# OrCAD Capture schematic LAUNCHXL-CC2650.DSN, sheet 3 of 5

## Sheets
3 4_XDS110: size A3
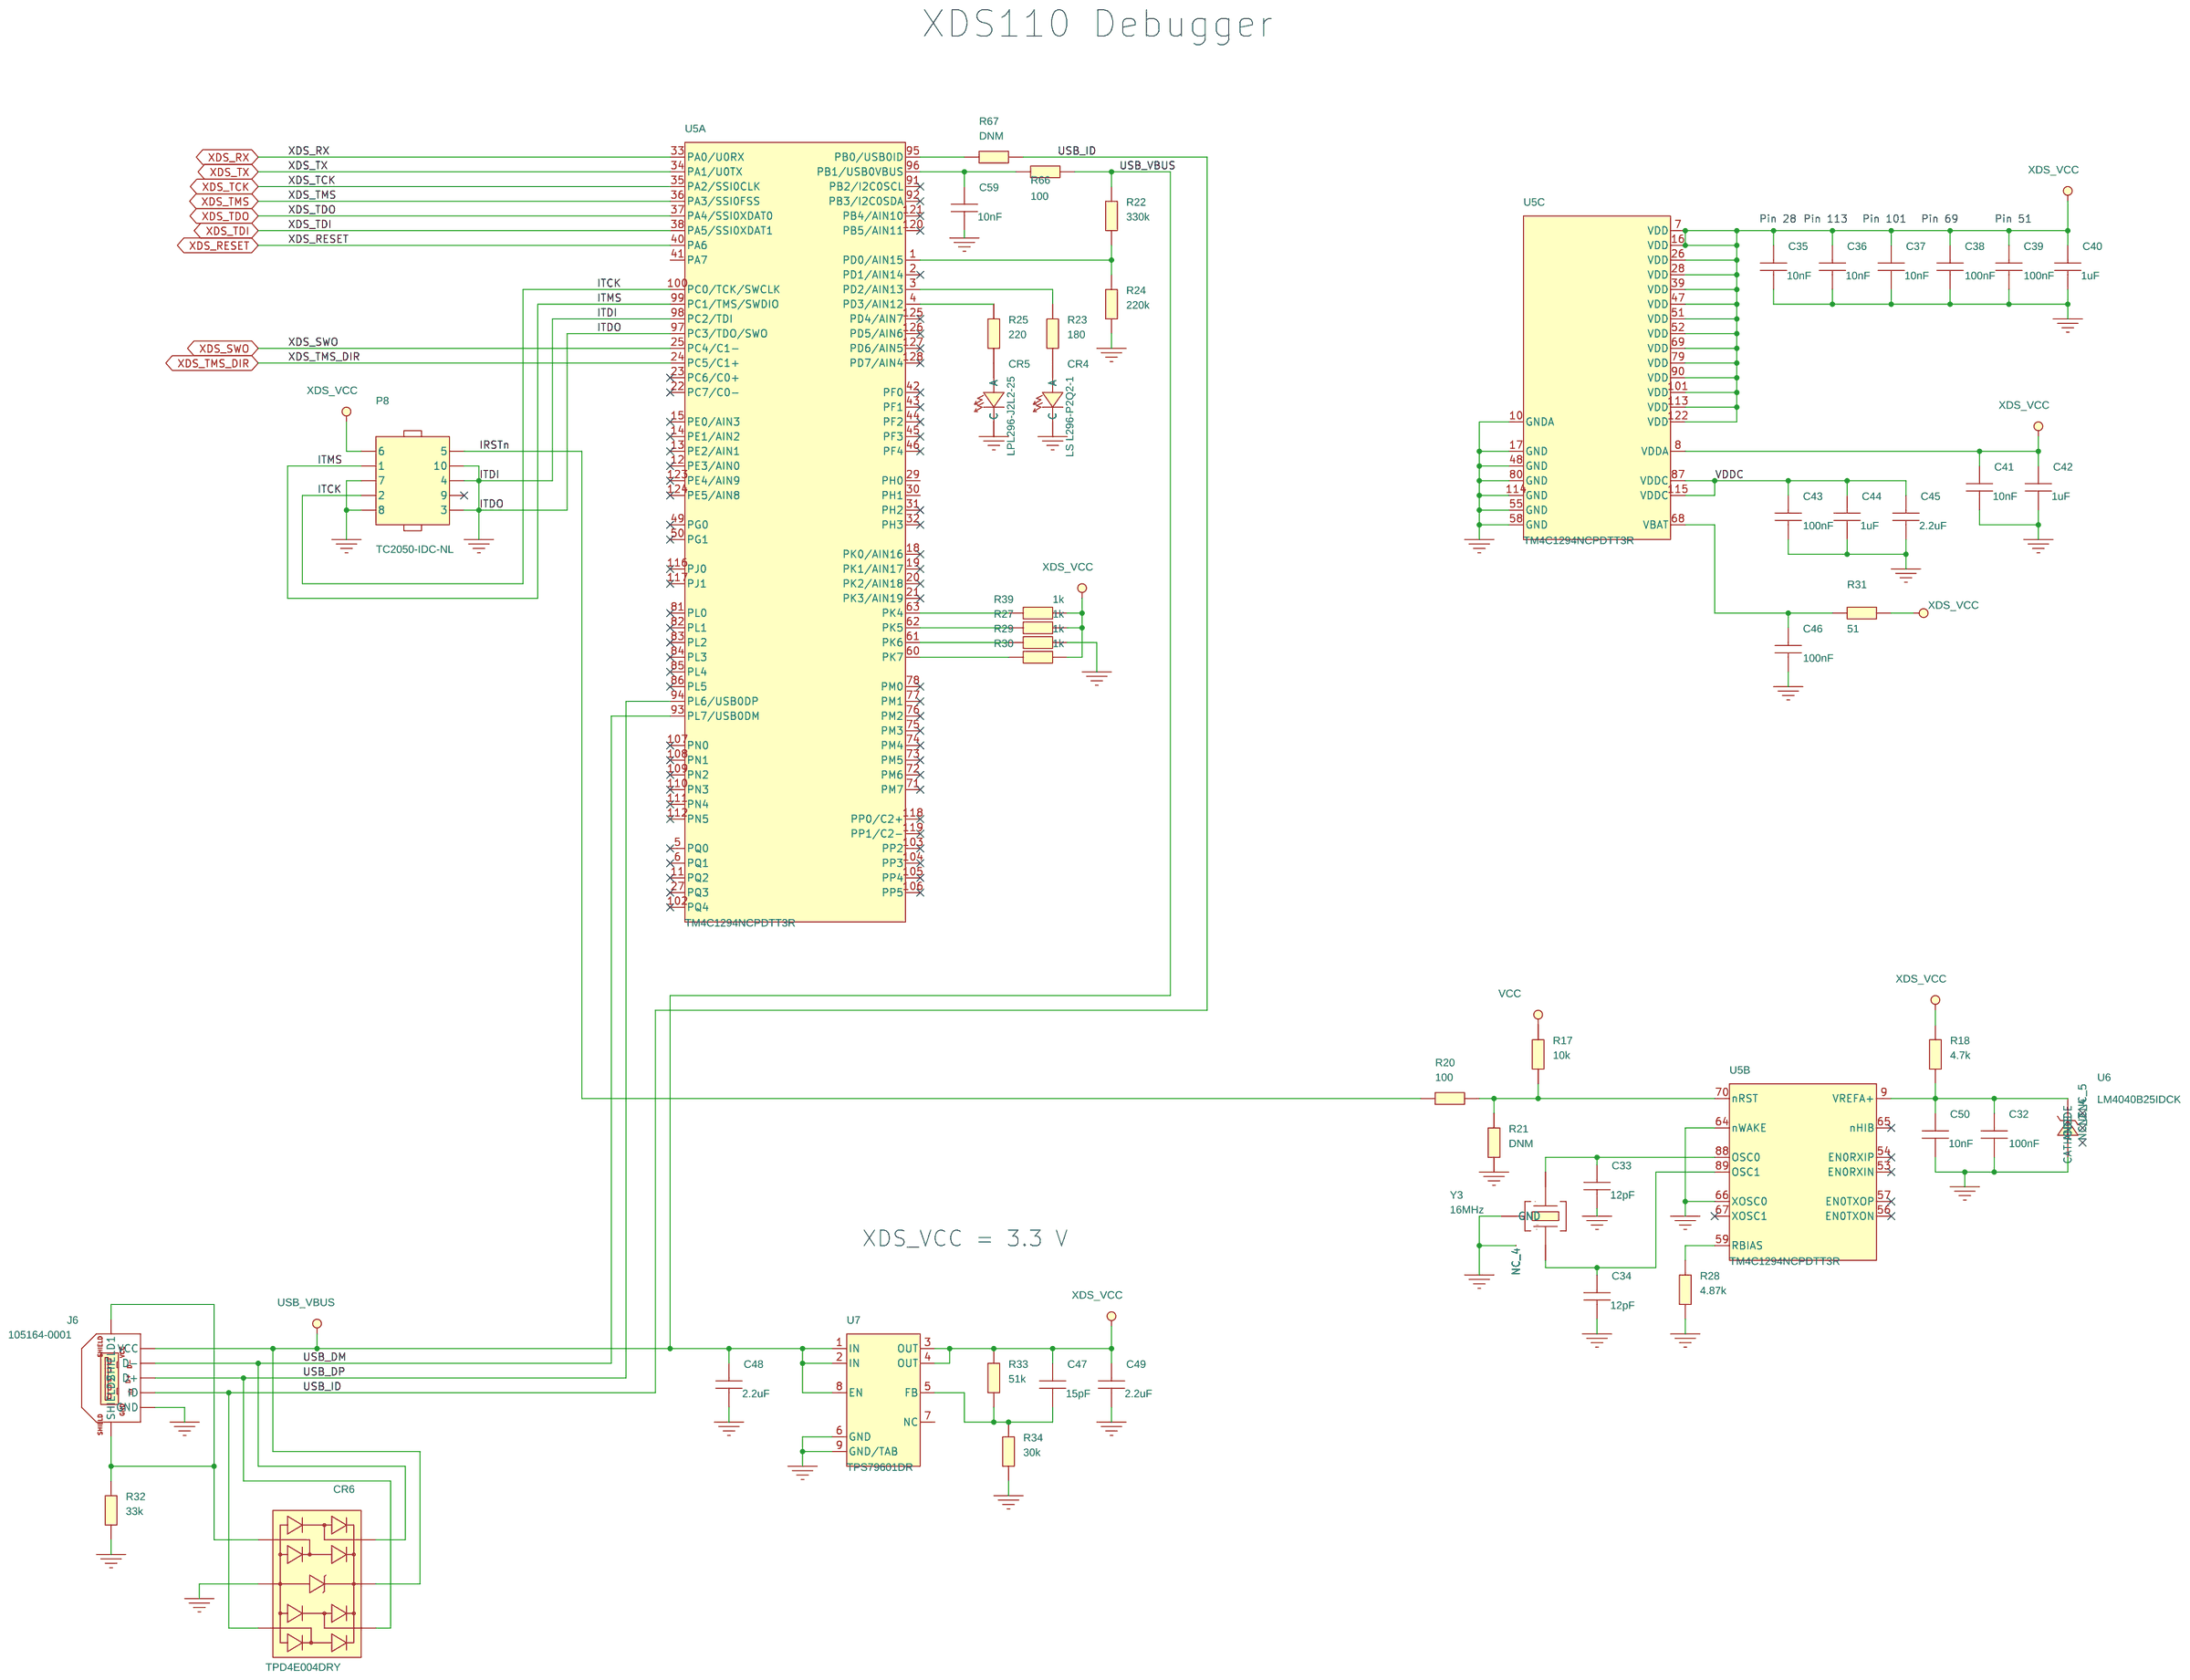
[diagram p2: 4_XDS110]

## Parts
C32  100nF  [CAPC1005X60B2N]
C33  12pF  [CAPC1005X60B2N]
C34  12pF  [CAPC1005X60B2N]
C35  10nF  [CAPC1005X60B2N]
C36  10nF  [CAPC1005X60B2N]
C37  10nF  [CAPC1005X60B2N]
C38  100nF  [CAPC1005X60B2N]
C39  100nF  [CAPC1005X60B2N]
C40  1uF  [CAPC1005X60B2N]
C41  10nF  [CAPC1005X60B2N]
C42  1uF  [CAPC1005X60B2N]
C43  100nF  [CAPC1005X60B2N]
C44  1uF  [CAPC1005X60B2N]
C45  2.2uF  [CAPC1005X60B2N]
C46  100nF  [CAPC1005X60B2N]
C47  15pF  [CAPC1005X60B2N]
C48  2.2uF  [CAPC1005X60B2N]
C49  2.2uF  [CAPC1005X60B2N]
C50  10nF  [CAPC1005X60B2N]
C59  10nF  [CAPC1005X60B2N]
CR4  LS L296-P2Q2-1  [LEDC1708X67L]
CR5  LPL296-J2L2-25  [LEDC1707X65L]
CR6  TPD4E004DRY  [SON50P100X145X60-6N]
J6  105164-0001  [MOLEX_1051640001_A2N]
P8  TC2050-IDC-NL  [TAGCONNECT_TC2050IDCNLN]
R17  10k  [RESC1005X40B2N]
R18  4.7k  [RESC1005X40B2N]
R20  100  [RESC1005X40B2N]
R21  DNM  [RESC1005X40B2N]
R22  330k  [RESC1005X40B2N]
R23  180  [RESC1005X40B2N]
R24  220k  [RESC1005X40B2N]
R25  220  [RESC1005X40B2N]
R27  1k  [RESC1005X40B2N]
R28  4.87k  [RESC1005X40B2N]
R29  1k  [RESC1005X40B2N]
R30  1k  [RESC1005X40B2N]
R31  51  [RESC1005X40B2N]
R32  33k  [RESC1005X40N]
R33  51k  [RESC1005X40B2N]
R34  30k  [RESC1005X40B2N]
R39  1k  [RESC1005X40B2N]
R66  100  [RESC1005X40B2N]
R67  DNM  [RESC1005X40B2N]
U5  TM4C1294NCPDTT3R  [QFP40P1600X1600X120-128N]  (sections A,B,C)
U6  LM4040B25IDCK  [SOT65P210X110-5N]
U7  TPS79601DR  [SON65P300X300X100-9AL]
Y3  16MHz  [OSCCC250X320X100-4BN]

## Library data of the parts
C32 C38 C39 C43 C46 = CAPACITOR: CAPACITOR, CERAMIC X7R, 100nF, 6.3V, -10%/+10%, -55DEGC/+125DEGC, 0402, SMD; AutoDoc File: https://notefied-dynamic-precision.com/DB/Apps/Desktop/Item/Object.aspx?id=113338; BU Name: TEXAS INSTRUMENTS NORWAY; Budget Currency: EUR; Budget Price: 0.007; Country of Origin: PHILIPPINES; Datasheet URL 1: http://psearch.murata.com/capacitor/product/GRM155R70J104KA01%23.pdf; Datasheet URL 2: http://search.murata.co.jp/Ceramy/image/img/w_hinm/L0005E.pdf; Dielectric Type: X7R; Last Time Buy: N/A; Lead Time: 14; LifeCycle Status: ACTIVE; MPN: GRM155R70J104KA01D; MPN Status: ACTIVE; Manufacturer: MURATA; Max Oper Temp: +125DEGC; Max Tol: +10%; Min Oper Temp: -55DEGC; Min Tol: -10%; Mounting Type: SMD; NOTE Status: PREFERRED; Old Footprint: CAPC1005X60N,0402; PCB Package: 0402; Packing Size: 10000; Packing Type: TAPE_&_REEL; Part Number: 02-07610; Part Type: CAPACITOR\CERAMIC\0402\STANDARD; Revision: R000; RoHS Status: ROHS_COMPLIANT; Rtd Voltage: 6.3V; Vendor: MURATA; Vendor Part Number: GRM155R70J104KA01D; Vendor Part Status: NRND; WEIGHT: 0.0016g
C33 C34 = CAPACITOR: CAPACITOR, CERAMIC C0G/NP0, 12pF, 50V, -5%/+5%, -55DEGC/+125DEGC, 0402, SMD; AutoDoc File: https://notefied-dynamic-precision.com/DB/Apps/Desktop/Item/Object.aspx?id=113340; BU Name: TEXAS INSTRUMENTS NORWAY; Budget Currency: USD; Budget Price: 0.00589; Country of Origin: MISSING INFO; Datasheet URL 1: N/A; Datasheet URL 2: N/A; Definied Quality: INDUSTRIAL; Dielectric Type: C0G/NP0; Esd Level: N/A; Last Time Buy: N/A; Lead Time: N/A; LifeCycle Status: ACTIVE; MPN: CAPACITOR_0402_12pF_C0G/NP0_M_+/-5%_50V; MPN Status: ACTIVE; MSL: N/A; MTBF: N/A; MTBF Standard: N/A; Manufacturer: MANUFACTURER SELECTION; Max Oper Temp: +125DEGC; Max Tol: +5%; Min Oper Temp: -55DEGC; Min Tol: -5%; Mounting Type: SMD; NOTE Status: PREFERRED; Old Footprint: CAPC1005X60N; PCB Package: 0402; Packing Size: 10000; Packing Type: TAPE_&_REEL; Part Number: 02-07612; Part Type: CAPACITOR\CERAMIC\0402\STANDARD; Revision: R000; RoHS Status: ROHS_COMPLIANT; Rtd Voltage: 50V; Vendor: MANUFACTURER SELECTION; Vendor Part Number: CAPACITOR_0402_12pF_C0G/NP0_M_+/-5%_50V; Vendor Part Status: ACTIVE; WEIGHT: N/A
C35-C37 C41 C50 C59 = CAPACITOR: CAPACITOR, CERAMIC X7R, 10nF, 25V, -10%/+10%, -55DEGC/+125DEGC, 0402, SMD; AutoDoc File: https://notefied-dynamic-precision.com/DB/Apps/Desktop/Item/Object.aspx?id=113343; BU Name: TEXAS INSTRUMENTS NORWAY; Budget Currency: USD; Budget Price: 0.00589; Country of Origin: MISSING INFO; Datasheet URL 1: N/A; Datasheet URL 2: N/A; Definied Quality: INDUSTRIAL; Dielectric Type: X7R; Esd Level: N/A; Last Time Buy: N/A; Lead Time: N/A; LifeCycle Status: ACTIVE; MPN: CAPACITOR_0402_10nF_X7R_M_+/-10%_25V; MPN Status: ACTIVE; MSL: N/A; MTBF: N/A; MTBF Standard: N/A; Manufacturer: MANUFACTURER SELECTION; Max Oper Temp: +125DEGC; Max Tol: +10%; Min Oper Temp: -55DEGC; Min Tol: -10%; Mounting Type: SMD; NOTE Status: PREFERRED; Old Footprint: CAPC1005X60N; PCB Package: 0402; Packing Size: 10000; Packing Type: TAPE_&_REEL; Part Number: 02-07615; Part Type: CAPACITOR\CERAMIC\0402\STANDARD; Revision: R000; RoHS Status: ROHS_COMPLIANT; Rtd Voltage: 25V; Vendor: MANUFACTURER SELECTION; Vendor Part Number: CAPACITOR_0402_10nF_X7R_M_+/-10%_25V; Vendor Part Status: ACTIVE; WEIGHT: N/A
C40 C42 C44 = CAPACITOR: CAPACITOR, CERAMIC X5R, 1uF, 10V, -10%/+10%, -55DEGC/+85DEGC, 0402, SMD; AutoDoc File: https://notefied-dynamic-precision.com/DB/Apps/Desktop/Item/Object.aspx?id=113339; BU Name: TEXAS INSTRUMENTS NORWAY; Budget Currency: EUR; Budget Price: 0.019; Country of Origin: PHILIPPINES,CHINA; Datasheet URL 1: http://psearch.murata.com/capacitor/product/GRM155R61A105KE15%23.pdf; Datasheet URL 2: http://search.murata.co.jp/Ceramy/image/img/w_hinm/L0005E.pdf; Definied Quality: INDUSTRIAL; Dielectric Type: X5R; Esd Level: N/A; Last Time Buy: N/A; Lead Time: 12; MPN: GRM155R61A105KE15D; MPN Status: ACTIVE; MSL: 1; MTBF: N/A; MTBF Standard: N/A; Manufacturer: MURATA; Max Oper Temp: +85DEGC; Max Tol: +10%; Min Oper Temp: -55DEGC; Min Tol: -10%; Mounting Type: SMD; NOTE Status: PREFERRED; Old Footprint: CAPC1005X60N,0402; PCB Package: 0402; Packing Size: 10000; Packing Type: TAPE_&_REEL; Part Number: 02-07611; Part Type: CAPACITOR\CERAMIC\0402\STANDARD; Revision: R000; RoHS Status: ROHS_COMPLIANT; Rtd Voltage: 10V; Vendor: MURATA; Vendor Part Number: GRM155R61A105KE15D; Vendor Part Status: NRND; WEIGHT: 0.0016g
C45 C48 C49 = CAPACITOR: CAPACITOR, CERAMIC X5R, 2.2uF, 6.3V, -10%/+10%, -55DEGC/+85DEGC, 0402, SMD; AutoDoc File: https://notefied-dynamic-precision.com/DB/Apps/Desktop/Item/Object.aspx?id=113352; BU Name: TEXAS INSTRUMENTS NORWAY; Budget Currency: USD; Budget Price: 0.0126; Country of Origin: PHILIPPINES; Datasheet URL 1: http://psearch.murata.com/capacitor/product/GRM155R60J225KE95%23.pdf; Datasheet URL 2: http://search.murata.co.jp/Ceramy/image/img/w_hinm/L0005E.pdf; Definied Quality: INDUSTRIAL; Dielectric Type: X5R; Esd Level: N/A; Last Time Buy: N/A; Lead Time: N/A; LifeCycle Status: NRND; MPN: GRM155R60J225KE95D; MPN Status: NRND; MSL: 1; MTBF: N/A; MTBF Standard: N/A; Manufacturer: MURATA; Max Oper Temp: +85DEGC; Max Tol: +10%; Min Oper Temp: -55DEGC; Min Tol: -10%; Mounting Type: SMD; NOTE Status: PREFERRED; Old Footprint: CAPC1005X60N; PCB Package: 0402; Packing Size: 10000; Packing Type: TAPE_&_REEL; Part Number: 02-07624; Part Type: CAPACITOR\CERAMIC\0402\STANDARD; Revision: R000; RoHS Status: ROHS_COMPLIANT; Rtd Voltage: 6.3V; Vendor: MURATA; Vendor Part Number: GRM155R60J225KE95D; Vendor Part Status: NRND; WEIGHT: 0.0016g
C47 = CAPACITOR: CAPACITOR, CERAMIC C0G/NP0, 15pF, 50V, -5%/+5%, -55DEGC/+125DEGC, 0402, SMD; AutoDoc File: https://notefied-dynamic-precision.com/DB/Apps/Desktop/Item/Object.aspx?id=113341; BU Name: TEXAS INSTRUMENTS NORWAY; Budget Currency: USD; Budget Price: 0.00589; Country of Origin: MISSING INFO; Datasheet URL 1: N/A; Datasheet URL 2: N/A; Definied Quality: INDUSTRIAL; Dielectric Type: C0G/NP0; Esd Level: N/A; Last Time Buy: N/A; Lead Time: N/A; LifeCycle Status: ACTIVE; MPN: CAPACITOR_0402_15pF_C0G/NP0_M_+/-5%_50V; MPN Status: ACTIVE; MSL: N/A; MTBF: N/A; MTBF Standard: N/A; Manufacturer: MANUFACTURER SELECTION; Max Oper Temp: +125DEGC; Max Tol: +5%; Min Oper Temp: -55DEGC; Min Tol: -5%; Mounting Type: SMD; NOTE Status: PREFERRED; Old Footprint: CAPC1005X60N; PCB Package: 0402; Packing Size: 10000; Packing Type: TAPE_&_REEL; Part Number: 02-07613; Part Type: CAPACITOR\CERAMIC\0402\STANDARD; Revision: R000; RoHS Status: ROHS_COMPLIANT; Rtd Voltage: 50V; Vendor: MANUFACTURER SELECTION; Vendor Part Number: CAPACITOR_0402_15pF_C0G/NP0_M_+/-5%_50V; Vendor Part Status: ACTIVE; WEIGHT: N/A
CR4 = LED: OPTO, LED, SUPER RED COLOR, 630nm, 1.8V TO 2.3V, 0.06A, 0603, SMD; ALT_SYMBOLS: LEDC1708X67L,LEDC1708X67M; AutoDoc File: http://notefied-dynamic-precision.com/DB/Apps/Desktop/Item/Object.aspx?id=88355; Budget Currency: USD; Budget Price: 0.089; Datasheet URL 1: http://www.osram-os.com/osram_os/en/products/product-catalog/led-light-emitting-diodes/smartled-0603/ls-l296/index.jsp?search_result=%2fosram_os%2fen%2fsearch%2fadvanced_search.jsp%3faction%3ddosearch%26inp_searchterm_1%3dLS%2bL296-P2Q2-1%26website_name%3; Datasheet URL 2: http://www.osram-os.com/Graphics/XPic5/00077119_0.pdf/LS%20L296%20-%20SMARTLED%200603.pdf; Definied Quality: INDUSTRIAL; Esd Level: HBM 2kV; FPLIST: LEDC1708X67N,LEDC1708X67L,LEDC1708X67M; Last Time Buy: N/A; Lead Time: 8; MPN Status: NRND; MSL: 2; MTBF: N/A; MTBF Standard: N/A; Manufacturer: OSRAM; Max Oper Temp: +100DEGC; Min Oper Temp: -40DEGC; Mounting Type: SMD; NOTE Status: PREFERRED; Old Footprint: LEDC1708X67N; PCB Package: 0603; PPCB Recomendation: Inactive for new design [Alert:0001]; Packing Size: 5000; Packing Type: TAPE_&_REEL; Part Number: 15-01169; Part Type: OPTO\LED\0603; Revision: R003; RoHS Status: ROHS_COMPLIANT; Rtd Current: 0.06A; Rtd Voltage: 1.8V TO 2.3V; WEIGHT: 0.002g
CR5 = LED: OPTO, LED, GREEN COLOR, 562nm, 0.02A, 0.08W, 0603, SMD; ALT_SYMBOLS: LEDC1707X65L,LEDC1707X65M; AutoDoc File: http://notefied-dynamic-precision.com/DB/Apps/Desktop/Item/Object.aspx?id=81622; Budget Currency: USD; Budget Price: 0.1263; Datasheet URL 1: N/A; Datasheet URL 2: http://catalog.osram-os.com/jsp/download.jsp?rootPath=/media/&name=LP_L296.pdf&docPath=Graphics/00077128_0.pdf&url=/media//_en/Graphics/00077128_0.pdf; Definied Quality: INDUSTRIAL; Esd Level: HBM 2kV; FPLIST: LEDC1707X65N,LEDC1707X65L,LEDC1707X65M; Last Time Buy: N/A; Lead Time: 8; MPN: LP L296-J2L2-25; MPN Status: NRND; MSL: 2; MTBF: N/A; MTBF Standard: N/A; Manufacturer: OSRAM; Max Oper Temp: +100DEGC; Min Oper Temp: -40DEGC; Mounting Type: SMD; NOTE Status: NOT_PREFERRED; Old Footprint: LEDC1707X65N; PCB Package: 0603; Packing Size: 5000; Packing Type: TAPE_&_REEL; Part Number: 15-01023; Part Type: OPTO\LED\0603; Revision: R003; RoHS Status: ROHS_COMPLIANT; Rtd Current: 0.02A; Rtd Power: 0.08W; Rtd Voltage: 2V; WEIGHT: 0.002g
CR6 = DIODE_TPD4E004_SON6: DIODE, PROTECTION, ESD ARRAY, 4 CHANNEL, 6V TO 8V, -40DEGC/+85DEGC, SON6, SMD; ALT_SYMBOLS: SON50P100X145X65-6L,SON50P100X145X65-6M; AutoDoc File: http://notefied-dynamic-precision.com/DB/Apps/Desktop/Item/Object.aspx?id=96191; Budget Currency: USD; Budget Price: 0.22; Datasheet URL 1: http://www.ti.com/lit/ml/mpds221e/mpds221e.pdf; Datasheet URL 2: http://www.ti.com/lit/ds/symlink/tpd4e004.pdf; Definied Quality: INDUSTRIAL; Esd Level: HBM 15kV; FPLIST: SON50P100X145X60-6N,SON50P100X145X65-6N,SON50P100X145X65-6L,SON50P100X145X65-6M; Last Time Buy: N/A; Lead Time: 10; MPN: TPD4E004DRYR; MPN Status: ACTIVE; MSL: 1; MTBF: 9.90*10^8; MTBF Standard: CL=60%,Ta=55degC,Tt=125degC,Ea=0.7eV; Manufacturer: TEXAS INSTRUMENTS; Max Oper Temp: +85DEGC; Min Oper Temp: -40DEGC; Mounting Type: SMD; NOTE Status: PREFERRED; Old Footprint: SON50P100X145X60-6N,SON50P100X145X65-6N; PCB Package: SON6; Packing Size: 5000; Packing Type: TAPE_&_REEL; Part Number: 14-06172; Part Type: DIODE\PROTECTION; Revision: R002; RoHS Status: ROHS_COMPLIANT; Rtd Voltage: 6V TO 8V; WEIGHT: 0.0028462g
J6 = CONN_USB_MICRO_B_2MH: CONNECTOR, USB, FEMALE, RIGHT ANGLE, 1 ROW, 5 PINS, PITCH 0.65mm, SMD; ALT_SYMBOLS: MOLEX_1051640001_A2L,MOLEX_1051640001_A2M; AutoDoc File: http://notefied-dynamic-precision.com/DB/Apps/Desktop/Item/Object.aspx?id=104390; Datasheet URL 1: http://www.molex.com/pdm_docs/sd/1051640001_sd.pdf; Datasheet URL 2: http://www.molex.com/webdocs/datasheets/pdf/en-us/1051640001_IO_CONNECTORS.pdf; FPLIST: MOLEX_1051640001_A2N,MOLEX_1051640001_A2L,MOLEX_1051640001_A2M; MPN Status: ACTIVE; Manufacturer: MOLEX; Max Oper Temp: +85DEGC; Min Oper Temp: -30DEGC; Mounting Type: SMD; NOTE Status: PREFERRED; No Of Pos: 5; No Of Rows: 1; Packing Type: TAPE_&_REEL; Part Number: 06-04998; Part Type: CONNECTOR\USB\MICRO_USB-B; Pitch: 0.65mm; Revision: R001; RoHS Status: ROHS_COMPLIANT; Rtd Current: 1.8V; Rtd Voltage: 30V; WEIGHT: 0.234g
P8 = CONN_IDC_TC2050-IDC-NL: NON COMPONENT, CONNECTOR CABLE, PLUG OF NAILS, 10 PINS, 2 ROWS, SMD; ALT_SYMBOLS: TAGCONNECT_TC2050IDCNLL,TAGCONNECT_TC2050IDCNLM; AutoDoc File: http://notefied-dynamic-precision.com/DB/Apps/Desktop/Item/Object.aspx?id=96644; FPLIST: TAGCONNECT_TC2050IDCNLN,TAGCONNECT_TC2050IDCNLL,TAGCONNECT_TC2050IDCNLM; Part Number: 19-00452; Part Type: NON_COMPONENT\CONNECTOR; Revision: R001
R17 = RESISTOR: RESISTOR, THICK FILM, 10k, -5%/+5%, 0.063W, 50V, -55DEGC/+155DEGC, 0402, SMD; AutoDoc File: https://notefied-dynamic-precision.com/DB/Apps/Desktop/Item/Object.aspx?id=113326; BU Name: TEXAS INSTRUMENTS NORWAY; Budget Currency: USD; Budget Price: 0.00244; Country of Origin: MISSING INFO; Datasheet URL 1: N/A; Datasheet URL 2: N/A; Definied Quality: INDUSTRIAL; Esd Level: N/A; Last Time Buy: N/A; Lead Time: N/A; LifeCycle Status: ACTIVE; MPN: RESISTOR_0402_10k_+/-5%_50V_0.063W_M_+/-200ppm; MPN Status: ACTIVE; MSL: N/A; MTBF: N/A; MTBF Standard: N/A; Manufacturer: MANUFACTURER SELECTION; Max Oper Temp: +155DEGC; Max TC: +200PPM/DEGC; Max Tol: +5%; Min Oper Temp: -55DEGC; Min TC: -200PPM/DEGC; Min Tol: -5%; Mounting Type: SMD; NOTE Status: PREFERRED; Old Footprint: RESC1005X40N; PCB Package: 0402; Packing Size: 10000; Packing Type: TAPE_&_REEL; Part Number: 01-22353; Part Type: RESISTOR\0402\STANDARD; Resistor Type: THICK FILM; Revision: R000; RoHS Status: ROHS_COMPLIANT; Rtd Current: N/A; Rtd Power: 0.063W; Rtd Voltage: 50V; Vendor: MANUFACTURER SELECTION; Vendor Part Number: RESISTOR_0402_10k_+/-5%_50V_0.063W_M_+/-200ppm; Vendor Part Status: ACTIVE; WEIGHT: N/A
R18 = RESISTOR: RESISTOR, THICK FILM, 4.7k, -5%/+5%, 0.063W, 50V, -55DEGC/+155DEGC, 0402, SMD; AutoDoc File: https://notefied-dynamic-precision.com/DB/Apps/Desktop/Item/Object.aspx?id=113325; BU Name: TEXAS INSTRUMENTS NORWAY; Budget Currency: USD; Budget Price: 0.00244; Country of Origin: MISSING INFO; Datasheet URL 1: N/A; Datasheet URL 2: N/A; Definied Quality: INDUSTRIAL; Esd Level: N/A; Last Time Buy: N/A; Lead Time: N/A; LifeCycle Status: ACTIVE; MPN: RESISTOR_0402_4.7k_+/-5%_50V_0.063W_M_+/-200ppm; MPN Status: ACTIVE; MSL: N/A; MTBF: N/A; MTBF Standard: N/A; Manufacturer: MANUFACTURER SELECTION; Max Oper Temp: +155DEGC; Max TC: +200PPM/DEGC; Max Tol: +5%; Min Oper Temp: -55DEGC; Min TC: -200PPM/DEGC; Min Tol: -5%; Mounting Type: SMD; NOTE Status: PREFERRED; Old Footprint: RESC1005X40N; PCB Package: 0402; Packing Size: 10000; Packing Type: TAPE_&_REEL; Part Number: 01-22352; Part Type: RESISTOR\0402\STANDARD; Resistor Type: THICK FILM; Revision: R000; RoHS Status: ROHS_COMPLIANT; Rtd Current: N/A; Rtd Power: 0.063W; Rtd Voltage: 50V; Vendor: MANUFACTURER SELECTION; Vendor Part Number: RESISTOR_0402_4.7k_+/-5%_50V_0.063W_M_+/-200ppm; Vendor Part Status: ACTIVE; WEIGHT: N/A
R20 = RESISTOR: RESISTOR, THICK FILM, 100, -1%/+1%, 0.063W, 50V, -55DEGC/+155DEGC, 0402, SMD; AutoDoc File: https://notefied-dynamic-precision.com/DB/Apps/Desktop/Item/Object.aspx?id=113330; BU Name: TEXAS INSTRUMENTS NORWAY; Budget Currency: USD; Budget Price: 0.00244; Country of Origin: MISSING INFO; Datasheet URL 1: N/A; Datasheet URL 2: N/A; Definied Quality: INDUSTRIAL; Esd Level: N/A; Last Time Buy: N/A; Lead Time: N/A; LifeCycle Status: ACTIVE; MPN: RESISTOR_0402_100_+/-1%_50V_0.063W_M_+/-100ppm; MPN Status: ACTIVE; MSL: N/A; MTBF: N/A; MTBF Standard: N/A; Manufacturer: MANUFACTURER SELECTION; Max Oper Temp: +155DEGC; Max TC: +100PPM/DEGC; Max Tol: +1%; Min Oper Temp: -55DEGC; Min TC: -100PPM/DEGC; Min Tol: -1%; Mounting Type: SMD; NOTE Status: PREFERRED; Old Footprint: RESC1005X40N; PCB Package: 0402; Packing Size: 10000; Packing Type: TAPE_&_REEL; Part Number: 01-22357; Part Type: RESISTOR\0402\PRECISION; Resistor Type: THICK FILM; Revision: R000; RoHS Status: ROHS_COMPLIANT; Rtd Current: N/A; Rtd Power: 0.063W; Rtd Voltage: 50V; Vendor: MANUFACTURER SELECTION; Vendor Part Number: RESISTOR_0402_100_+/-1%_50V_0.063W_M_+/-100ppm; Vendor Part Status: ACTIVE; WEIGHT: N/A
R21 R67 = RESISTOR: RESISTOR, DO NOT MOUNT, 0402, SMD; AutoDoc File: https://notefied-dynamic-precision.com/DB/Apps/Desktop/Item/Object.aspx?id=113312; BU Name: TEXAS INSTRUMENTS NORWAY; Budget Currency: N/A; Budget Price: N/A; Country of Origin: MISSING INFO; Datasheet URL 1: N/A; Datasheet URL 2: N/A; Esd Level: N/A; Last Time Buy: N/A; Lead Time: N/A; LifeCycle Status: ACTIVE; MPN Status: ACTIVE; MSL: N/A; MTBF: N/A; MTBF Standard: N/A; Manufacturer: DO NOT MOUNT; Max Oper Temp: N/A; Max TC: N/A; Max Tol: N/A; Min Oper Temp: N/A; Min TC: N/A; Min Tol: N/A; Mounting Type: SMD; NOTE Status: PREFERRED; Old Footprint: RESC1005X40N,0402; PCB Package: 0402; Packing Size: N/A; Part Number: 01-22339; Part Type: RESISTOR\0402\STANDARD; Resistance: N/A; Resistor Type: THICK FILM; Revision: R000; RoHS Status: MISSING_INFO; Rtd Current: N/A; Rtd Power: N/A; Rtd Voltage: N/A; Vendor: DO NOT MOUNT; Vendor Part Status: ACTIVE; WEIGHT: N/A
R22 = RESISTOR: RESISTOR, THICK FILM, 330k, -1%/+1%, 0.063W, 50V, -55DEGC/+155DEGC, 0402, SMD; AutoDoc File: https://notefied-dynamic-precision.com/DB/Apps/Desktop/Item/Object.aspx?id=113335; BU Name: TEXAS INSTRUMENTS NORWAY; Budget Currency: USD; Budget Price: 0.00244; Country of Origin: MISSING INFO; Datasheet URL 1: N/A; Datasheet URL 2: N/A; Definied Quality: INDUSTRIAL; Esd Level: N/A; Last Time Buy: N/A; Lead Time: N/A; LifeCycle Status: ACTIVE; MPN: RESISTOR_0402_330k_+/-1%_50V_0.063W_M_+/-100ppm; MPN Status: ACTIVE; MSL: N/A; MTBF: N/A; MTBF Standard: N/A; Manufacturer: MANUFACTURER SELECTION; Max Oper Temp: +155DEGC; Max TC: +100PPM/DEGC; Max Tol: +1%; Min Oper Temp: -55DEGC; Min TC: -100PPM/DEGC; Min Tol: -1%; Mounting Type: SMD; NOTE Status: PREFERRED; Old Footprint: RESC1005X40N; PCB Package: 0402; Packing Size: 10000; Packing Type: TAPE_&_REEL; Part Number: 01-22362; Part Type: RESISTOR\0402\PRECISION; Resistor Type: THICK FILM; Revision: R000; RoHS Status: ROHS_COMPLIANT; Rtd Current: N/A; Rtd Power: 0.063W; Rtd Voltage: 50V; Vendor: MANUFACTURER SELECTION; Vendor Part Number: RESISTOR_0402_330k_+/-1%_50V_0.063W_M_+/-100ppm; Vendor Part Status: ACTIVE; WEIGHT: N/A
R23 = RESISTOR: RESISTOR, THICK FILM, 180, -5%/+5%, 0.063W, 50V, -55DEGC/+155DEGC, 0402, SMD; AutoDoc File: https://notefied-dynamic-precision.com/DB/Apps/Desktop/Item/Object.aspx?id=113318; BU Name: TEXAS INSTRUMENTS NORWAY; Budget Currency: USD; Budget Price: 0.00244; Country of Origin: MISSING INFO; Datasheet URL 1: N/A; Datasheet URL 2: N/A; Definied Quality: INDUSTRIAL; Esd Level: N/A; Last Time Buy: N/A; Lead Time: N/A; LifeCycle Status: ACTIVE; MPN: RESISTOR_0402_180_+/-5%_50V_0.063W_M_+/-200ppm; MPN Status: ACTIVE; MSL: N/A; MTBF: N/A; MTBF Standard: N/A; Manufacturer: MANUFACTURER SELECTION; Max Oper Temp: +155DEGC; Max TC: +200PPM/DEGC; Max Tol: +5%; Min Oper Temp: -55DEGC; Min TC: -200PPM/DEGC; Min Tol: -5%; Mounting Type: SMD; NOTE Status: PREFERRED; Old Footprint: RESC1005X40N; PCB Package: 0402; Packing Size: 10000; Packing Type: TAPE_&_REEL; Part Number: 01-22345; Part Type: RESISTOR\0402\STANDARD; Resistor Type: THICK FILM; Revision: R000; RoHS Status: ROHS_COMPLIANT; Rtd Current: N/A; Rtd Power: 0.063W; Rtd Voltage: 50V; Vendor: MANUFACTURER SELECTION; Vendor Part Number: RESISTOR_0402_180_+/-5%_50V_0.063W_M_+/-200ppm; Vendor Part Status: ACTIVE; WEIGHT: N/A
R24 = RESISTOR: RESISTOR, THICK FILM, 220k, -1%/+1%, 0.063W, 50V, -55DEGC/+155DEGC, 0402, SMD; AutoDoc File: https://notefied-dynamic-precision.com/DB/Apps/Desktop/Item/Object.aspx?id=113334; BU Name: TEXAS INSTRUMENTS NORWAY; Budget Currency: USD; Budget Price: 0.00244; Country of Origin: MISSING INFO; Datasheet URL 1: N/A; Datasheet URL 2: N/A; Definied Quality: INDUSTRIAL; Esd Level: N/A; Last Time Buy: N/A; Lead Time: N/A; LifeCycle Status: ACTIVE; MPN: RESISTOR_0402_220k_+/-1%_50V_0.063W_M_+/-100ppm; MPN Status: ACTIVE; MSL: N/A; MTBF: N/A; MTBF Standard: N/A; Manufacturer: MANUFACTURER SELECTION; Max Oper Temp: +155DEGC; Max TC: +100PPM/DEGC; Max Tol: +1%; Min Oper Temp: -55DEGC; Min TC: -100PPM/DEGC; Min Tol: -1%; Mounting Type: SMD; NOTE Status: PREFERRED; Old Footprint: RESC1005X40N; PCB Package: 0402; Packing Size: 10000; Packing Type: TAPE_&_REEL; Part Number: 01-22361; Part Type: RESISTOR\0402\PRECISION; Resistor Type: THICK FILM; Revision: R000; RoHS Status: ROHS_COMPLIANT; Rtd Current: N/A; Rtd Power: 0.063W; Rtd Voltage: 50V; Vendor: MANUFACTURER SELECTION; Vendor Part Number: RESISTOR_0402_220k_+/-1%_50V_0.063W_M_+/-100ppm; Vendor Part Status: ACTIVE; WEIGHT: N/A
R25 = RESISTOR: RESISTOR, THICK FILM, 220, -5%/+5%, 0.063W, 50V, -55DEGC/+155DEGC, 0402, SMD; AutoDoc File: https://notefied-dynamic-precision.com/DB/Apps/Desktop/Item/Object.aspx?id=113319; BU Name: TEXAS INSTRUMENTS NORWAY; Budget Currency: USD; Budget Price: 0.00244; Country of Origin: MISSING INFO; Datasheet URL 1: N/A; Datasheet URL 2: N/A; Definied Quality: INDUSTRIAL; Esd Level: N/A; Last Time Buy: N/A; Lead Time: N/A; LifeCycle Status: ACTIVE; MPN: RESISTOR_0402_220_+/-5%_50V_0.063W_M_+/-200ppm; MPN Status: ACTIVE; MSL: N/A; MTBF: N/A; MTBF Standard: N/A; Manufacturer: MANUFACTURER SELECTION; Max Oper Temp: +155DEGC; Max TC: +200PPM/DEGC; Max Tol: +5%; Min Oper Temp: -55DEGC; Min TC: -200PPM/DEGC; Min Tol: -5%; Mounting Type: SMD; NOTE Status: PREFERRED; Old Footprint: RESC1005X40N; PCB Package: 0402; Packing Size: 10000; Packing Type: TAPE_&_REEL; Part Number: 01-22346; Part Type: RESISTOR\0402\STANDARD; Resistor Type: THICK FILM; Revision: R000; RoHS Status: ROHS_COMPLIANT; Rtd Current: N/A; Rtd Power: 0.063W; Rtd Voltage: 50V; Vendor: MANUFACTURER SELECTION; Vendor Part Number: RESISTOR_0402_220_+/-5%_50V_0.063W_M_+/-200ppm; Vendor Part Status: ACTIVE; WEIGHT: N/A
R27 R29 R30 R39 = RESISTOR: RESISTOR, THICK FILM, 1k, -5%/+5%, 0.063W, 50V, -55DEGC/+155DEGC, 0402, SMD; AutoDoc File: https://notefied-dynamic-precision.com/DB/Apps/Desktop/Item/Object.aspx?id=113322; BU Name: TEXAS INSTRUMENTS NORWAY; Budget Currency: USD; Budget Price: 0.00244; Country of Origin: MISSING INFO; Datasheet URL 1: N/A; Datasheet URL 2: N/A; Definied Quality: INDUSTRIAL; Esd Level: N/A; Last Time Buy: N/A; Lead Time: N/A; LifeCycle Status: ACTIVE; MPN: RESISTOR_0402_1k_+/-5%_50V_0.063W_M_+/-200ppm; MPN Status: ACTIVE; MSL: N/A; MTBF: N/A; MTBF Standard: N/A; Manufacturer: MANUFACTURER SELECTION; Max Oper Temp: +155DEGC; Max TC: +200PPM/DEGC; Max Tol: +5%; Min Oper Temp: -55DEGC; Min TC: -200PPM/DEGC; Min Tol: -5%; Mounting Type: SMD; NOTE Status: PREFERRED; Old Footprint: RESC1005X40N; PCB Package: 0402; Packing Size: 10000; Packing Type: TAPE_&_REEL; Part Number: 01-22349; Part Type: RESISTOR\0402\STANDARD; Resistor Type: THICK FILM; Revision: R000; RoHS Status: ROHS_COMPLIANT; Rtd Current: N/A; Rtd Power: 0.063W; Rtd Voltage: 50V; Vendor: MANUFACTURER SELECTION; Vendor Part Number: RESISTOR_0402_1k_+/-5%_50V_0.063W_M_+/-200ppm; Vendor Part Status: ACTIVE; WEIGHT: N/A
R28 = RESISTOR: RESISTOR, THICK FILM, 4.87k, -1%/+1%, 0.063W, 50V, -55DEGC/+155DEGC, 0402, SMD; AutoDoc File: https://notefied-dynamic-precision.com/DB/Apps/Desktop/Item/Object.aspx?id=113331; BU Name: TEXAS INSTRUMENTS NORWAY; Budget Currency: USD; Budget Price: 0.00244; Country of Origin: MISSING INFO; Datasheet URL 1: N/A; Datasheet URL 2: N/A; Definied Quality: INDUSTRIAL; Esd Level: N/A; Last Time Buy: N/A; Lead Time: N/A; LifeCycle Status: ACTIVE; MPN: RESISTOR_0402_4.87k_+/-1%_50V_0.063W_M_+/-100ppm; MPN Status: ACTIVE; MSL: N/A; MTBF: N/A; MTBF Standard: N/A; Manufacturer: MANUFACTURER SELECTION; Max Oper Temp: +155DEGC; Max TC: +100PPM/DEGC; Max Tol: +1%; Min Oper Temp: -55DEGC; Min TC: -100PPM/DEGC; Min Tol: -1%; Mounting Type: SMD; NOTE Status: PREFERRED; Old Footprint: RESC1005X40N; PCB Package: 0402; Packing Size: 10000; Packing Type: TAPE_&_REEL; Part Number: 01-22358; Part Type: RESISTOR\0402\PRECISION; Resistor Type: THICK FILM; Revision: R000; RoHS Status: ROHS_COMPLIANT; Rtd Current: N/A; Rtd Power: 0.063W; Rtd Voltage: 50V; Vendor: MANUFACTURER SELECTION; Vendor Part Number: RESISTOR_0402_4.87k_+/-1%_50V_0.063W_M_+/-100ppm; Vendor Part Status: ACTIVE; WEIGHT: N/A
R31 = RESISTOR: RESISTOR, THICK FILM, 51, -5%/+5%, 0.063W, 50V, -55DEGC/+155DEGC, 0402, SMD; AutoDoc File: https://notefied-dynamic-precision.com/DB/Apps/Desktop/Item/Object.aspx?id=113315; BU Name: TEXAS INSTRUMENTS NORWAY; Budget Currency: USD; Budget Price: 0.00244; Country of Origin: MISSING INFO; Datasheet URL 1: N/A; Datasheet URL 2: N/A; Definied Quality: INDUSTRIAL; Esd Level: N/A; Last Time Buy: N/A; Lead Time: N/A; LifeCycle Status: ACTIVE; MPN: RESISTOR_0402_51_+/-5%_50V_0.063W_M_+/-200ppm; MPN Status: ACTIVE; MSL: N/A; MTBF: N/A; MTBF Standard: N/A; Manufacturer: MANUFACTURER SELECTION; Max Oper Temp: +155DEGC; Max TC: +200PPM/DEGC; Max Tol: +5%; Min Oper Temp: -55DEGC; Min TC: -200PPM/DEGC; Min Tol: -5%; Mounting Type: SMD; NOTE Status: PREFERRED; Old Footprint: RESC1005X40N; PCB Package: 0402; Packing Size: 10000; Packing Type: TAPE_&_REEL; Part Number: 01-22342; Part Type: RESISTOR\0402\STANDARD; Resistor Type: THICK FILM; Revision: R000; RoHS Status: ROHS_COMPLIANT; Rtd Current: N/A; Rtd Power: 0.063W; Rtd Voltage: 50V; Vendor: MANUFACTURER SELECTION; Vendor Part Number: RESISTOR_0402_51_+/-5%_50V_0.063W_M_+/-200ppm; Vendor Part Status: ACTIVE; WEIGHT: N/A
R32 = RESISTOR: RESISTOR, THICK FILM, 33k, -1%/+1%, 0.063W, 50V, -55DEGC/+155DEGC, 0402, SMD; ALT_SYMBOLS: RESC1005X40L,RESC1005X40M; AutoDoc File: http://notefied-dynamic-precision.com/DB/Apps/Desktop/Item/Object.aspx?id=76835; Budget Currency: USD; Budget Price: 0.00244; Datasheet URL 1: N/A; Datasheet URL 2: N/A; Definied Quality: INDUSTRIAL; Esd Level: N/A; FPLIST: RESC1005X40N,RESC1005X40L,RESC1005X40M; Last Time Buy: N/A; Lead Time: N/A; LifeCycle Status: ACTIVE; MPN: RESISTOR_0402_33k_+/-1%_50V_0.063W_M_+/-100PPM; MPN Status: ACTIVE; MSL: N/A; MTBF: N/A; MTBF Standard: N/A; Manufacturer: MANUFACTURER SELECTION; Max Oper Temp: +155DEGC; Max TC: +100PPM/DEGC; Max Tol: +1%; Min Oper Temp: -55DEGC; Min TC: -100PPM/DEGC; Min Tol: -1%; Mounting Type: SMD; NOTE Status: PREFERRED; PCB Package: 0402; Packing Size: 10000; Packing Type: TAPE_&_REEL; Part Number: 01-12780; Part Type: RESISTOR\0402\PRECISION; Resistor Type: THICK FILM; Revision: R001; RoHS Status: ROHS_COMPLIANT; Rtd Power: 0.063W; Rtd Voltage: 50V; WEIGHT: N/A
R33 = RESISTOR: RESISTOR, THICK FILM, 51k, -5%/+5%, 0.063W, 50V, -55DEGC/+155DEGC, 0402, SMD; AutoDoc File: https://notefied-dynamic-precision.com/DB/Apps/Desktop/Item/Object.aspx?id=113328; BU Name: TEXAS INSTRUMENTS NORWAY; Budget Currency: USD; Budget Price: 0.00244; Country of Origin: MISSING INFO; Datasheet URL 1: N/A; Datasheet URL 2: N/A; Definied Quality: INDUSTRIAL; Esd Level: N/A; Last Time Buy: N/A; Lead Time: N/A; LifeCycle Status: ACTIVE; MPN: RESISTOR_0402_51k_+/-5%_50V_0.063W_M_+/-200ppm; MPN Status: ACTIVE; MSL: N/A; MTBF: N/A; MTBF Standard: N/A; Manufacturer: MANUFACTURER SELECTION; Max Oper Temp: +155DEGC; Max TC: +200PPM/DEGC; Max Tol: +5%; Min Oper Temp: -55DEGC; Min TC: -200PPM/DEGC; Min Tol: -5%; Mounting Type: SMD; NOTE Status: PREFERRED; Old Footprint: RESC1005X40N; PCB Package: 0402; Packing Size: 10000; Packing Type: TAPE_&_REEL; Part Number: 01-22355; Part Type: RESISTOR\0402\STANDARD; Resistor Type: THICK FILM; Revision: R000; RoHS Status: ROHS_COMPLIANT; Rtd Current: N/A; Rtd Power: 0.063W; Rtd Voltage: 50V; Vendor: MANUFACTURER SELECTION; Vendor Part Number: RESISTOR_0402_51k_+/-5%_50V_0.063W_M_+/-200ppm; Vendor Part Status: ACTIVE; WEIGHT: N/A
R34 = RESISTOR: RESISTOR, THICK FILM, 30k, -5%/+5%, 0.063W, 50V, -55DEGC/+155DEGC, 0402, SMD; AutoDoc File: https://notefied-dynamic-precision.com/DB/Apps/Desktop/Item/Object.aspx?id=113327; BU Name: TEXAS INSTRUMENTS NORWAY; Budget Currency: USD; Budget Price: 0.00244; Country of Origin: MISSING INFO; Datasheet URL 1: N/A; Datasheet URL 2: N/A; Definied Quality: INDUSTRIAL; Esd Level: N/A; Last Time Buy: N/A; Lead Time: N/A; LifeCycle Status: ACTIVE; MPN: RESISTOR_0402_30k_+/-5%_50V_0.063W_M_+/-200ppm; MPN Status: ACTIVE; MSL: N/A; MTBF: N/A; MTBF Standard: N/A; Manufacturer: MANUFACTURER SELECTION; Max Oper Temp: +155DEGC; Max TC: +200PPM/DEGC; Max Tol: +5%; Min Oper Temp: -55DEGC; Min TC: -200PPM/DEGC; Min Tol: -5%; Mounting Type: SMD; NOTE Status: PREFERRED; Old Footprint: RESC1005X40N; PCB Package: 0402; Packing Size: 10000; Packing Type: TAPE_&_REEL; Part Number: 01-22354; Part Type: RESISTOR\0402\STANDARD; Resistor Type: THICK FILM; Revision: R000; RoHS Status: ROHS_COMPLIANT; Rtd Current: N/A; Rtd Power: 0.063W; Rtd Voltage: 50V; Vendor: MANUFACTURER SELECTION; Vendor Part Number: RESISTOR_0402_30k_+/-5%_50V_0.063W_M_+/-200ppm; Vendor Part Status: ACTIVE; WEIGHT: N/A
R66 = RESISTOR: RESISTOR, THICK FILM, 100, -5%/+5%, 0.063W, 50V, -55DEGC/+155DEGC, 0402, SMD; AutoDoc File: https://notefied-dynamic-precision.com/DB/Apps/Desktop/Item/Object.aspx?id=113316; BU Name: TEXAS INSTRUMENTS NORWAY; Budget Currency: USD; Budget Price: 0.00244; Country of Origin: MISSING INFO; Datasheet URL 1: N/A; Datasheet URL 2: N/A; Definied Quality: INDUSTRIAL; Esd Level: N/A; Last Time Buy: N/A; Lead Time: N/A; LifeCycle Status: ACTIVE; MPN: RESISTOR_0402_100_+/-5%_50V_0.063W_M_+/-200ppm; MPN Status: ACTIVE; MSL: N/A; MTBF: N/A; MTBF Standard: N/A; Manufacturer: MANUFACTURER SELECTION; Max Oper Temp: +155DEGC; Max TC: +200PPM/DEGC; Max Tol: +5%; Min Oper Temp: -55DEGC; Min TC: -200PPM/DEGC; Min Tol: -5%; Mounting Type: SMD; NOTE Status: PREFERRED; Old Footprint: RESC1005X40N; PCB Package: 0402; Packing Size: 10000; Packing Type: TAPE_&_REEL; Part Number: 01-22343; Part Type: RESISTOR\0402\STANDARD; Resistor Type: THICK FILM; Revision: R000; RoHS Status: ROHS_COMPLIANT; Rtd Current: N/A; Rtd Power: 0.063W; Rtd Voltage: 50V; Vendor: MANUFACTURER SELECTION; Vendor Part Number: RESISTOR_0402_100_+/-5%_50V_0.063W_M_+/-200ppm; Vendor Part Status: ACTIVE; WEIGHT: N/A
U5 = IC_PROC_TM4C1294NCPDT_TQFP128: IC, MICROPROCESSOR, TIVA C SERIES MICROCONTROLLER, ARM CRTEX-M4, 2.97V TO 3.63V, TQFP128, SMD; ALT_SYMBOLS: QFP40P1600X1600X120-128L,QFP40P1600X1600X120-128M; AutoDoc File: http://notefied-dynamic-precision.com/DB/Apps/Desktop/Item/Object.aspx?id=96468; Budget Currency: USD; Budget Price: 8.47; Datasheet URL 1: N/A; Datasheet URL 2: http://www.ti.com/lit/ds/symlink/tm4c1294ncpdt.pdf; FPLIST: QFP40P1600X1600X120-128N,QFP40P1600X1600X120-128L,QFP40P1600X1600X120-128M; MPN Status: ACTIVE; MSL: 3; Manufacturer: TEXAS INSTRUMENTS; Max Oper Temp: +85DEGC; Min Oper Temp: -40DEGC; Mounting Type: SMD; NOTE Status: PREFERRED; PCB Package: TQFP128; Packing Size: 500; Packing Type: TAPE_&_REEL; Part Number: 18-29511; Part Type: IC\PROCESSOR\TEXAS; Revision: R001; RoHS Status: ROHS_COMPLIANT; Rtd Voltage: 2.97V TO 3.63V
U6 = IC_REF_LM4040_SC70-5: IC, ANALOG, PRECISION MICROPOWER SHUNT VOLTAGE REFERENCE, 2.5V, SC70-5, SMD; ALT_SYMBOLS: SOT65P210X110-5L,SOT65P210X110-5M; AutoDoc File: http://notefied-dynamic-precision.com/DB/Apps/Desktop/Item/Object.aspx?id=96645; Budget Currency: USD; Budget Price: 0.78; Datasheet URL 1: http://www.ti.com/lit/ml/mpds025f/mpds025f.pdf; Datasheet URL 2: http://www.ti.com/lit/ds/symlink/lm4040b25.pdf; Definied Quality: INDUSTRIAL; Esd Level: N/A; FPLIST: SOT65P210X110-5N,SOT65P210X110-5L,SOT65P210X110-5M; Last Time Buy: N/A; Lead Time: 7; MPN: LM4040B25IDCKR; MPN Status: ACTIVE; MSL: 1; Manufacturer: TEXAS INSTRUMENTS; Max Oper Temp: +85DEGC; Min Oper Temp: -40DEGC; Mounting Type: SMD; NOTE Status: PREFERRED; PCB Package: SC70-5; Packing Size: 3000; Packing Type: TAPE_&_REEL; Part Number: 18-29558; Part Type: IC\ANALOG\PM\REFERENCE; Revision: R001; RoHS Status: ROHS_COMPLIANT; Rtd Voltage: 2.5V; WEIGHT: 0.011098173g
U7 = IC_PM_TPS79601_SON8: IC, ANALOG, ULTRALOW-NOISE, HIGH PSRR, FAST, RF, 1A LOW-DROPOUT LINEAR REGULATORS, VIN:2.7V TO 5.5V, VOUT:1.2V TO 5.5V, SON8, SMD; ALT_SYMBOLS: SON65P300X300X100-9AL,SON65P300X300X100-9AM; AutoDoc File: http://notefied-dynamic-precision.com/DB/Apps/Desktop/Item/Object.aspx?id=96546; Budget Currency: USD; Budget Price: 1; Datasheet URL 1: http://www.ti.com/litv/pdf/mpds118j; Datasheet URL 2: http://www.ti.com/lit/ds/symlink/tps79601.pdf; FPLIST: SON65P300X300X100-9AN,SON65P300X300X100-9AL,SON65P300X300X100-9AM; LifeCycle Status: ACTIVE; MPN: TPS79601DRBR; MPN Status: ACTIVE; MSL: 2; Manufacturer: TEXAS INSTRUMENTS; Max Oper Temp: +125DEGC; Min Oper Temp: -40DEGC; Mounting Type: SMD; NOTE Status: PREFERRED; Old Footprint: SON65P300X300X100-9AN; PCB Package: SON8; Packing Size: 3000; Packing Type: TAPE_&_REEL; Part Number: 18-29530; Part Type: IC\ANALOG\PM\REGULATOR; Revision: R001; RoHS Status: ROHS_COMPLIANT; Rtd Voltage: 1.2V TO 5.4V; WEIGHT: 0.024660813g
Y3 = XTAL_4: CRYSTAL, OSCILLATOR, 16MHz, -30PPM/DEGC/+30PPM/DEGC, -40DEGC/+85DEGC, SMD; ALT_SYMBOLS: OSCCC250X320X100-4BL,OSCCC250X320X100-4BM; AutoDoc File: http://notefied-dynamic-precision.com/DB/Apps/Desktop/Item/Object.aspx?id=96470; Datasheet URL 1: N/A; Datasheet URL 2: http://www.ndk.com/images/products/catalog/c_NX3225GA-STD-CRG-2_e.pdf; FPLIST: OSCCC250X320X100-4BN,OSCCC250X320X100-4BL,OSCCC250X320X100-4BM; MPN: NX3225GA-16.000M-STD-CRG-1; MPN Status: ACTIVE; Manufacturer: NIHON DEMPA KOGYO; Max Oper Temp: +85DEGC; Max TC: +30PPM/DEGC; Max Tol: +20PPM; Min Oper Temp: -40DEGC; Min TC: -30PPM/DEGC; Min Tol: -20PPM; Mounting Type: SMD; NOTE Status: PREFERRED; Part Number: 12-00745; Part Type: CRYSTAL\OSCILLATOR; Revision: R001; RoHS Status: ROHS_COMPLIANT

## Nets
GND: C32.2 C33.2 C34.2 C35.2 C36.2 C37.2 C38.2 C39.2 C40.2 C41.2 C42.2 C43.2 C44.2 C45.2 C46.2 C48.2 C49.2 C50.2 C59.2 CR4.1(C) CR5.1(C) CR6.3 J6.5(GND) P8.3(7) P8.5(8) P8.9(10) R21.2 R24.2 R28.1 R29.2 R32.1 R34.1 U5.10(GNDA) U5.17(GND) U5.48(GND) U5.55(GND) U5.58(GND) U5.64(nWAKE) U5.66(XOSC0) U5.80(GND) U5.114(GND) U6.1(ANODE) U7.6(GND) U7.9(GND/TAB) Y3.2(GND) Y3.4(NC) ; also on sheet 1 2 4 5
VDDC: C43.1 C44.1 C45.1 U5.87(VDDC) U5.115(VDDC)
IRSTn: P8.10(5) R20.2
ITCK: P8.4(2) U5.100(PC0/TCK/SWCLK)
ITDI: P8.8(4) U5.98(PC2/TDI)
ITDO: P8.6(3) U5.97(PC3/TDO/SWO)
ITMS: P8.2(1) U5.99(PC1/TMS/SWDIO)
USB_DM: CR6.5 J6.2(D-) U5.93(PL7/USB0DM)
USB_DP: CR6.4 J6.3(D+) U5.94(PL6/USB0DP)
USB_ID: CR6.2 J6.4(ID) R67.1
USB_VBUS: C48.1 CR6.6 J6.1(VCC) R22.2 R66.1 U7.1(IN) U7.2(IN) U7.8(EN) ; also on sheet 2
XDS_RESET: U5.40(PA6) ; also on sheet 2
XDS_RX: U5.33(PA0/U0RX) ; also on sheet 2
XDS_SWO: U5.25(PC4/C1-) ; also on sheet 2
XDS_TCK: U5.35(PA2/SSI0CLK) ; also on sheet 2
XDS_TDI: U5.38(PA5/SSI0XDAT1) ; also on sheet 2
XDS_TDO: U5.37(PA4/SSI0XDAT0) ; also on sheet 2
XDS_TMS: U5.36(PA3/SSI0FSS) ; also on sheet 2
XDS_TMS_DIR: U5.24(PC5/C1+) ; also on sheet 2
XDS_TX: U5.34(PA1/U0TX) ; also on sheet 2
XDS_VCC: C35.1 C36.1 C37.1 C38.1 C39.1 C40.1 C41.1 C42.1 C47.1 C49.1 P8.1(6) R17.2 R18.2 R27.1 R30.2 R31.2 R33.2 R39.1 U5.7(VDD) U5.8(VDDA) U5.16(VDD) U5.26(VDD) U5.28(VDD) U5.39(VDD) U5.47(VDD) U5.51(VDD) U5.52(VDD) U5.69(VDD) U5.79(VDD) U5.90(VDD) U5.101(VDD) U5.113(VDD) U5.122(VDD) U7.3(OUT) U7.4(OUT) ; also on sheet 2
N949215: R17.1 R20.1 R21.1 U5.70(nRST)
N949243: R30.1 U5.60(PK7)
N949263: C47.2 R33.1 R34.2 U7.5(FB)
N949375: R28.2 U5.59(RBIAS)
N949517: R22.1 R24.1 U5.1(PD0/AIN15)
N949687: C34.1 U5.89(OSC1) Y3.3
N949695: C33.1 U5.88(OSC0) Y3.1
N950083: C32.1 C50.1 R18.1 U5.9(VREFA+) U6.3(CATHODE)
N950235: R67.2 U5.95(PB0/USB0ID)
N951001: R39.2 U5.63(PK4)
N951013: R29.1 U5.61(PK6)
N951017: R27.2 U5.62(PK5)
N952443: C46.1 R31.1 U5.68(VBAT)
N1004371: R23.2 U5.3(PD2/AIN13)
N1004534: R25.2 U5.4(PD3/AIN12)
N1031635: CR6.1 J6.M1(SHIELD1) J6.M2(SHIELD2) R32.2
N1432281: C59.1 R66.2 U5.96(PB1/USB0VBUS)
N1444594: CR4.2(A) R23.1
N1444595: CR5.2(A) R25.1

Not connected (* = marked no-connect by the designer): P8 7(9)*; U5 2(PD1/AIN14)* 5(PQ0)* 6(PQ1)* 11(PQ2)* 12(PE3/AIN0)* 13(PE2/AIN1)* 14(PE1/AIN2)* 15(PE0/AIN3)* 18(PK0/AIN16)* 19(PK1/AIN17)* 20(PK2/AIN18)* 21(PK3/AIN19)* 22(PC7/C0-)* 23(PC6/C0+)* 27(PQ3)* 29(PH0) 30(PH1) 31(PH2)* 32(PH3)* 41(PA7) 42(PF0)* 43(PF1)* 44(PF2)* 45(PF3)* 46(PF4)* 49(PG0)* 50(PG1)* 53(EN0RXIN)* 54(EN0RXIP)* 56(EN0TXON)* 57(EN0TXOP)* 65(nHIB)* 67(XOSC1)* 71(PM7)* 72(PM6)* 73(PM5)* 74(PM4)* 75(PM3)* 76(PM2)* 77(PM1)* 78(PM0)* 81(PL0)* 82(PL1)* 83(PL2)* 84(PL3)* 85(PL4)* 86(PL5)* 91(PB2/I2C0SCL)* 92(PB3/I2C0SDA)* 102(PQ4)* 103(PP2)* 104(PP3)* 105(PP4)* 106(PP5)* 107(PN0)* 108(PN1)* 109(PN2)* 110(PN3)* 111(PN4)* 112(PN5)* 116(PJ0)* 117(PJ1)* 118(PP0/C2+)* 119(PP1/C2-)* 120(PB5/AIN11)* 121(PB4/AIN10)* 123(PE4/AIN9)* 124(PE5/AIN8)* 125(PD4/AIN7)* 126(PD5/AIN6)* 127(PD6/AIN5)* 128(PD7/AIN4)*; U6 2(NC)* 4(NC)* 5(NC)*; U7 7(NC)

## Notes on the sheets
sheet 3
- XDS110 Debugger
- Pin 28
- Pin 113
- Pin 101
- Pin 69
- Pin 51
- XDS_VCC = 3.3 V
